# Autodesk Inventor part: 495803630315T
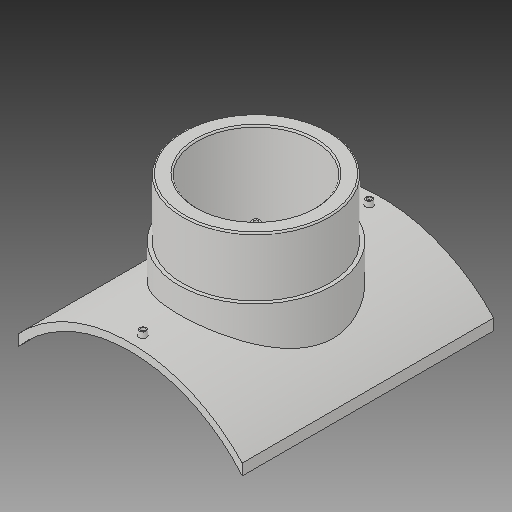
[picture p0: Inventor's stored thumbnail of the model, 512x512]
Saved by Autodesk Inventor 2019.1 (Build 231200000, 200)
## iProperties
Created: 2017-10
Part Number: 495803630315T
Material: Generic
Description: PLASSON BRANCH SADDLE 630x315
Document SubType Name: Modeling
Designer: KIM
Mass: 2754.05 g
Surface Area: 3037.44 cm^2
Volume: 2754.05 cm^3
Density: 1 g/cm^3
Appearance: Default
Author: KIM
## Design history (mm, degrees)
derived "495803.ipt"
feature "Solid1::495803.ipt"
tag "TaggingFeature1"
body "Solid1"
other parameters: "d1" = 16, "d2" = 481, "d4" = 0, "d12" = 342.1, "d13" = 14, "d14" = 243, "d16" = 5 deg, "d18" = 4, "d19" = 14, "d20" = 0, "d21" = 3, "d22" = 0, "d23" = 511, "d24" = 330.75, "d25" = 16, "d26" = 252, "d28" = 0, "d29" = 9.6, "d31" = 0, "d33" = 0, "d34" = 6.3, "d36" = 315, "d37" = 126, "d38" = 0, "d39" = 3.15, "d_1" = 315, "B_" = 481, "x_" = 16, "D_" = 16
